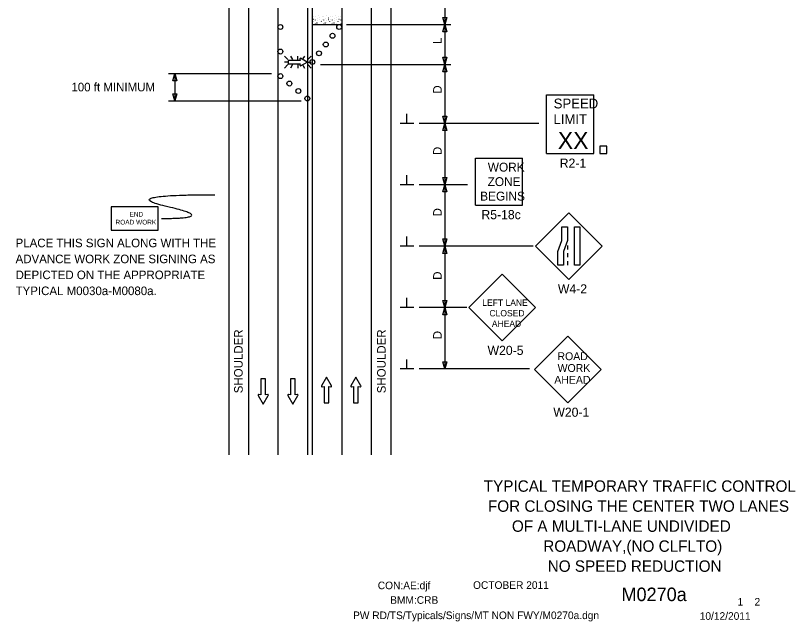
# Model space of a CAD drawing. Extents: x 16796 to 18475, y 7218 to 8209.
# Drawn here: x 16796 to 17431, y 7218 to 7712 of the extents above; entities that cross this region are included whole.
import ezdxf

# ---------------------------------------------------------------- set-up
doc = ezdxf.new("R2010")
doc.units = 0
for name, color, linetype in [('ALI_LEGAL_EX', 7, 'Continuous'), ('BORDER', 7, 'Continuous'), ('BORDER_SIGNAL_WO', 7, 'Continuous'), ('MT_SCRATCH_LEVEL_E', 7, 'Continuous'), ('PAVT_EDGE_EX', 7, 'Continuous'), ('TRAFFIC_SIGNS_PR', 7, 'Continuous'), ('TYPICAL_TEXT_DIMEN_PR', 7, 'Continuous')]:
    doc.layers.add(name, color=color, linetype=linetype)

msp = doc.modelspace()

# ---------------------------------------------------------------- linework, layer by layer
at = {"layer": 'ALI_LEGAL_EX'}
for p, q in [((17009.33, 8204.89), (17009.33, 7353.77)), ((17061.33, 8204.89), (17061.33, 7353.77))]:
    msp.add_line(p, q, dxfattribs=at)
for points in [[(17009.33, 7704.89), (17009.33, 7679.89)], [(17009.33, 7604.89), (17009.33, 7579.89)], [(17061.33, 7604.89), (17061.33, 7579.89)], [(17009.33, 7504.89), (17009.33, 7479.89)], [(17061.33, 7504.89), (17061.33, 7479.89)], [(17009.33, 7404.89), (17009.33, 7379.89)], [(17061.33, 7404.89), (17061.33, 7379.89)]]:
    msp.add_lwpolyline(points, dxfattribs=at)
at = {"layer": 'MT_SCRATCH_LEVEL_E'}
for p, q in [((16999.25, 7415.83), (16995.51, 7415.83)), ((16995.51, 7415.83), (16995.51, 7402.58)), ((16999.25, 7415.83), (16995.51, 7415.83)), ((16995.51, 7415.83), (16995.51, 7402.58)), ((16999.25, 7402.58), (16999.25, 7415.83)), ((16999.25, 7402.58), (16999.25, 7415.83)), ((17023.43, 7415.83), (17019.69, 7415.83)), ((17019.69, 7415.83), (17019.69, 7402.58)), ((17023.43, 7415.83), (17019.69, 7415.83)), ((17019.69, 7415.83), (17019.69, 7402.58)), ((17023.43, 7402.58), (17023.43, 7415.83)), ((17023.43, 7402.58), (17023.43, 7415.83)), ((17048.93, 7417.12), (17044.82, 7409.88)), ((17048.93, 7417.12), (17044.82, 7409.88)), ((17053.07, 7409.88), (17048.93, 7417.12)), ((17053.07, 7409.88), (17048.93, 7417.12)), ((17072.85, 7417.12), (17068.74, 7409.88)), ((17072.85, 7417.12), (17068.74, 7409.88)), ((17077, 7409.88), (17072.85, 7417.12)), ((17077, 7409.88), (17072.85, 7417.12)), ((17045.3, 7409.19), (17047.08, 7409.51)), ((17045.3, 7409.19), (17047.08, 7409.51)), ((17047.08, 7409.51), (17047.08, 7396.25)), ((17047.08, 7409.51), (17047.08, 7396.25)), ((17050.82, 7396.25), (17050.82, 7409.51)), ((17050.82, 7409.51), (17052.6, 7409.19)), ((17050.82, 7396.25), (17050.82, 7409.51)), ((17050.82, 7409.51), (17052.6, 7409.19)), ((17069.22, 7409.19), (17071, 7409.51)), ((17069.22, 7409.19), (17071, 7409.51)), ((17071, 7409.51), (17071, 7396.25)), ((17071, 7409.51), (17071, 7396.25)), ((17074.74, 7396.25), (17074.74, 7409.51)), ((17074.74, 7409.51), (17076.52, 7409.19)), ((17074.74, 7396.25), (17074.74, 7409.51)), ((17074.74, 7409.51), (17076.52, 7409.19)), ((16993.25, 7402.21), (16997.4, 7394.97)), ((16993.25, 7402.21), (16997.4, 7394.97)), ((16995.51, 7402.58), (16993.73, 7402.89)), ((16995.51, 7402.58), (16993.73, 7402.89)), ((16997.4, 7394.97), (17001.51, 7402.21)), ((16997.4, 7394.97), (17001.51, 7402.21)), ((17001.03, 7402.89), (16999.25, 7402.58)), ((17001.03, 7402.89), (16999.25, 7402.58)), ((17017.44, 7402.21), (17021.58, 7394.97)), ((17017.44, 7402.21), (17021.58, 7394.97)), ((17019.69, 7402.58), (17017.91, 7402.89)), ((17019.69, 7402.58), (17017.91, 7402.89)), ((17021.58, 7394.97), (17025.69, 7402.21)), ((17021.58, 7394.97), (17025.69, 7402.21)), ((17025.21, 7402.89), (17023.43, 7402.58)), ((17025.21, 7402.89), (17023.43, 7402.58)), ((17047.08, 7396.25), (17050.82, 7396.25)), ((17047.08, 7396.25), (17050.82, 7396.25)), ((17071, 7396.25), (17074.74, 7396.25)), ((17071, 7396.25), (17074.74, 7396.25))]:
    msp.add_line(p, q, dxfattribs=at)
for centre, start, end in [((17045.22, 7409.65), 150.42484, 279.96381), ((17045.22, 7409.65), 150.42484, 279.96381), ((17052.66, 7409.66), 260.03619, 29.77312), ((17052.66, 7409.66), 260.03619, 29.77312), ((17069.15, 7409.65), 150.42484, 279.96381), ((17069.15, 7409.65), 150.42484, 279.96381), ((17076.59, 7409.66), 260.03619, 29.77312), ((17076.59, 7409.66), 260.03619, 29.77312), ((16993.66, 7402.43), 80.03619, 209.77312), ((16993.66, 7402.43), 80.03619, 209.77312), ((17001.1, 7402.43), 330.42484, 99.96381), ((17001.1, 7402.43), 330.42484, 99.96381), ((17017.84, 7402.43), 80.03619, 209.77312), ((17017.84, 7402.43), 80.03619, 209.77312), ((17025.28, 7402.43), 330.42484, 99.96381), ((17025.28, 7402.43), 330.42484, 99.96381)]:
    msp.add_arc(centre, 0.463, start, end, dxfattribs=at)
at = {"layer": 'PAVT_EDGE_EX'}
for p, q in [((16969.33, 8204.89), (16969.33, 7353.77)), ((16985.33, 8204.89), (16985.33, 7353.77)), ((17085.33, 8204.89), (17085.33, 7353.77)), ((17101.33, 8204.89), (17101.33, 7353.77)), ((17033.33, 7728.31), (17033.33, 7353.77)), ((17037.33, 7728.31), (17037.33, 7353.77)), ((17042.2, 7711.53), (17042.25, 7711.45)), ((17049.09, 7711.53), (17049.14, 7711.45)), ((17055.98, 7711.53), (17056.03, 7711.45)), ((17037.81, 7706.89), (17037.86, 7707.01)), ((17038.38, 7710.85), (17038.43, 7710.77)), ((17038.43, 7708.64), (17038.48, 7708.56)), ((17039.71, 7708.07), (17039.72, 7707.95)), ((17039.91, 7710.71), (17039.96, 7710.63)), ((17040.6, 7705.65), (17040.65, 7705.57)), ((17041.33, 7705.62), (17041.38, 7705.54)), ((17041.55, 7708.92), (17041.6, 7709.04)), ((17041.74, 7707.72), (17041.79, 7707.64)), ((17043.48, 7709.79), (17043.53, 7709.71)), ((17043.52, 7708.39), (17043.57, 7708.51)), ((17044.7, 7706.89), (17044.75, 7707.01)), ((17045.27, 7710.85), (17045.32, 7710.77)), ((17045.32, 7708.64), (17045.37, 7708.56)), ((17046.6, 7708.07), (17046.61, 7707.95)), ((17046.8, 7710.71), (17046.85, 7710.63)), ((17047.48, 7705.65), (17047.53, 7705.57)), ((17048.22, 7705.62), (17048.27, 7705.54)), ((17048.44, 7708.92), (17048.49, 7709.04)), ((17048.63, 7707.72), (17048.68, 7707.64)), ((17050.37, 7709.79), (17050.42, 7709.71)), ((17050.41, 7708.39), (17050.46, 7708.51)), ((17051.59, 7706.89), (17051.64, 7707.01)), ((17052.16, 7710.85), (17052.21, 7710.77)), ((17052.21, 7708.64), (17052.26, 7708.56)), ((17053.49, 7708.07), (17053.5, 7707.95)), ((17053.69, 7710.71), (17053.74, 7710.63)), ((17054.37, 7705.65), (17054.42, 7705.57)), ((17055.11, 7705.62), (17055.16, 7705.54)), ((17055.33, 7708.92), (17055.38, 7709.04)), ((17055.52, 7707.72), (17055.57, 7707.64)), ((17057.25, 7709.79), (17057.31, 7709.71)), ((17057.3, 7708.39), (17057.35, 7708.51)), ((17058.47, 7706.89), (17058.53, 7707.01)), ((17059.04, 7710.85), (17059.1, 7710.77)), ((17059.09, 7708.64), (17059.14, 7708.56)), ((17060.37, 7708.07), (17060.39, 7707.95)), ((17060.57, 7710.71), (17060.63, 7710.63)), ((17061.26, 7705.65), (17061.31, 7705.57)), ((17037.33, 7704.33), (17061.33, 7704.33)), ((17039.83, 7704.69), (17039.88, 7704.81)), ((17043.65, 7704.39), (17043.7, 7704.51)), ((17046.72, 7704.69), (17046.77, 7704.81)), ((17050.54, 7704.39), (17050.59, 7704.51)), ((17053.61, 7704.69), (17053.66, 7704.81)), ((17057.42, 7704.39), (17057.48, 7704.51)), ((17060.49, 7704.69), (17060.55, 7704.81))]:
    msp.add_line(p, q, dxfattribs=at)
at = {"layer": 'TRAFFIC_SIGNS_PR'}
for p, q in [((17017.4, 7675.79), (17014.58, 7678.61)), ((17017.4, 7673.76), (17014.58, 7673.76)), ((17019.7, 7678.61), (17021.33, 7675.79)), ((17025.49, 7675.79), (17025.49, 7678.61)), ((17030.96, 7678.61), (17029.75, 7676.52)), ((17036.39, 7678.61), (17033.58, 7675.79)), ((17033.58, 7673.76), (17036.39, 7673.76)), ((17017.4, 7671.73), (17014.58, 7668.91)), ((17021.35, 7671.73), (17019.73, 7668.91)), ((17025.49, 7671.73), (17025.49, 7668.91)), ((17029.67, 7671.09), (17030.93, 7668.91)), ((17036.39, 7668.91), (17033.58, 7671.73)), ((17228.22, 7647.13), (17266.62, 7647.13)), ((17228.22, 7599.13), (17228.22, 7647.13)), ((17266.62, 7599.13), (17266.62, 7647.13)), ((17228.22, 7599.13), (17266.62, 7599.13)), ((17170.3, 7557.18), (17170.3, 7595.58)), ((17170.3, 7595.58), (17208.7, 7595.58)), ((17208.7, 7557.18), (17208.7, 7595.58)), ((17170.3, 7557.18), (17208.7, 7557.18)), ((17246.44, 7551), (17219.29, 7523.85)), ((17273.6, 7523.85), (17246.44, 7551)), ((17219.29, 7523.85), (17246.44, 7496.7)), ((17245.2, 7524.34), (17245.2, 7521.14)), ((17246.44, 7496.7), (17273.6, 7523.85)), ((17245.2, 7517.94), (17245.2, 7514.74)), ((17245.2, 7511.54), (17245.2, 7508.34)), ((17191.93, 7500.91), (17164.78, 7473.76)), ((17219.08, 7473.76), (17191.93, 7500.91)), ((17164.78, 7473.76), (17191.93, 7446.61)), ((17191.93, 7446.61), (17219.08, 7473.76)), ((17245.52, 7450.52), (17218.37, 7423.37)), ((17272.67, 7423.37), (17245.52, 7450.52)), ((17218.37, 7423.37), (17245.52, 7396.22)), ((17245.52, 7396.22), (17272.67, 7423.37))]:
    msp.add_line(p, q, dxfattribs=at)
for points in [[(17027.32, 7676.44), (17027.55, 7675.15), (17017.82, 7675.15), (17017.82, 7672.4), (17027.55, 7672.4), (17027.31, 7671.1)], [(17027.82, 7670.74), (17033.13, 7673.76), (17027.82, 7676.8)]]:
    msp.add_lwpolyline(points, dxfattribs=at)
for points in [[(17271.64, 7599.13), (17277.23, 7599.13), (17277.23, 7605.3), (17271.64, 7605.3)], [(16873.44, 7536.69), (16911.84, 7536.69), (16911.84, 7555.89), (16873.44, 7555.89)], [(17245.2, 7539.59), (17245.2, 7528.4), (17241.85, 7519.52), (17241.85, 7508.34), (17237.36, 7508.34), (17237.36, 7519.52), (17240.7, 7528.4), (17240.7, 7539.59)], [(17255.33, 7539.59), (17255.33, 7508.34), (17250.84, 7508.34), (17250.84, 7539.59)]]:
    msp.add_lwpolyline(points, close=True, dxfattribs=at)
for centre in [(17011.37, 7702.3), (17059.3, 7702.3), (17053.81, 7695.16), (17048.32, 7688.03), (17011.37, 7682.3), (17042.83, 7680.9), (17037.33, 7673.77), (17011.37, 7662.3), (17018.69, 7656.24), (17026.02, 7650.17), (17033.34, 7644.1)]:
    msp.add_circle(centre, 2, dxfattribs=at)
for centre, start, end in [((17027.65, 7676.5), 61.48329, 189.95933), ((17027.65, 7671.04), 170.73078, 298.89165)]:
    msp.add_arc(centre, 0.341, start, end, dxfattribs=at)
msp.add_open_spline([(16914.38, 7546.34), (16961.61, 7546.34), (16876.59, 7565.69), (16958.07, 7565.69)], degree=2, dxfattribs=at)
at = {"layer": 'TYPICAL_TEXT_DIMEN_PR'}
for p, q in [((17145.33, 7728.31), (17145.33, 7704.31)), ((17145.33, 7704.31), (17143.76, 7710.17)), ((17143.76, 7710.17), (17145.33, 7710.17)), ((17145.33, 7710.17), (17146.9, 7710.17)), ((17146.9, 7710.17), (17145.33, 7704.31)), ((17065.19, 7704.31), (17150.33, 7704.31)), ((17143.76, 7698.44), (17145.33, 7704.31)), ((17143.76, 7698.44), (17145.33, 7704.31)), ((17145.33, 7704.31), (17145.33, 7671.77)), ((17145.33, 7704.31), (17146.9, 7698.44)), ((17145.33, 7704.31), (17146.9, 7698.44)), ((17145.33, 7698.44), (17143.76, 7698.44)), ((17145.33, 7698.44), (17143.76, 7698.44)), ((17146.9, 7698.44), (17145.33, 7698.44)), ((17146.9, 7698.44), (17145.33, 7698.44)), ((17145.33, 7671.77), (17143.76, 7677.63)), ((17143.76, 7677.63), (17145.33, 7677.63)), ((17145.33, 7671.77), (17143.76, 7677.63)), ((17143.76, 7677.63), (17145.33, 7677.63)), ((17145.33, 7677.63), (17146.9, 7677.63)), ((17146.9, 7677.63), (17145.33, 7671.77)), ((17145.33, 7677.63), (17146.9, 7677.63)), ((17146.9, 7677.63), (17145.33, 7671.77)), ((17043.9, 7671.77), (17150.33, 7671.77)), ((17143.76, 7665.9), (17145.33, 7671.77)), ((17143.76, 7665.9), (17145.33, 7671.77)), ((17145.33, 7671.77), (17145.33, 7623.77)), ((17145.33, 7671.77), (17146.9, 7665.9)), ((17145.33, 7671.77), (17146.9, 7665.9)), ((16920.33, 7664.31), (17003.99, 7664.31)), ((16923.76, 7658.44), (16925.33, 7664.31)), ((16925.33, 7664.31), (16925.33, 7642.1)), ((16925.33, 7664.31), (16926.9, 7658.44)), ((17145.33, 7665.9), (17143.76, 7665.9)), ((17145.33, 7665.9), (17143.76, 7665.9)), ((17146.9, 7665.9), (17145.33, 7665.9)), ((17146.9, 7665.9), (17145.33, 7665.9)), ((16925.33, 7658.44), (16923.76, 7658.44)), ((16926.9, 7658.44), (16925.33, 7658.44)), ((16920.33, 7642.1), (17028.2, 7642.1)), ((16925.33, 7642.1), (16923.76, 7647.96)), ((16923.76, 7647.96), (16925.33, 7647.96)), ((16925.33, 7647.96), (16926.9, 7647.96)), ((16926.9, 7647.96), (16925.33, 7642.1)), ((17114.46, 7623.77), (17114.46, 7631.56)), ((17145.33, 7623.77), (17143.76, 7629.64)), ((17143.76, 7629.64), (17145.33, 7629.64)), ((17145.33, 7623.77), (17143.76, 7629.64)), ((17143.76, 7629.64), (17145.33, 7629.64)), ((17145.33, 7629.64), (17146.9, 7629.64)), ((17146.9, 7629.64), (17145.33, 7623.77)), ((17145.33, 7629.64), (17146.9, 7629.64)), ((17146.9, 7629.64), (17145.33, 7623.77)), ((17120.08, 7623.77), (17108.83, 7623.77)), ((17221.76, 7623.77), (17124.33, 7623.77)), ((17143.76, 7617.91), (17145.33, 7623.77)), ((17143.76, 7617.91), (17145.33, 7623.77)), ((17145.33, 7623.77), (17145.33, 7573.77)), ((17145.33, 7623.77), (17146.9, 7617.91)), ((17145.33, 7623.77), (17146.9, 7617.91)), ((17145.33, 7617.91), (17143.76, 7617.91)), ((17145.33, 7617.91), (17143.76, 7617.91)), ((17146.9, 7617.91), (17145.33, 7617.91)), ((17146.9, 7617.91), (17145.33, 7617.91)), ((17114.46, 7573.77), (17114.46, 7581.56)), ((17145.33, 7573.77), (17143.76, 7579.64)), ((17143.76, 7579.64), (17145.33, 7579.64)), ((17145.33, 7573.77), (17143.76, 7579.64)), ((17143.76, 7579.64), (17145.33, 7579.64)), ((17145.33, 7579.64), (17146.9, 7579.64)), ((17146.9, 7579.64), (17145.33, 7573.77)), ((17145.33, 7579.64), (17146.9, 7579.64)), ((17146.9, 7579.64), (17145.33, 7573.77)), ((17120.08, 7573.77), (17108.83, 7573.77)), ((17163.91, 7573.77), (17124.33, 7573.77)), ((17143.76, 7567.91), (17145.33, 7573.77)), ((17145.33, 7573.77), (17145.33, 7523.77)), ((17145.33, 7573.77), (17146.9, 7567.91)), ((17145.33, 7567.91), (17143.76, 7567.91)), ((17146.9, 7567.91), (17145.33, 7567.91)), ((17114.46, 7523.77), (17114.46, 7531.56)), ((17145.33, 7523.77), (17143.76, 7529.64)), ((17143.76, 7529.64), (17145.33, 7529.64)), ((17145.33, 7529.64), (17146.9, 7529.64)), ((17146.9, 7529.64), (17145.33, 7523.77)), ((17120.08, 7523.77), (17108.83, 7523.77)), ((17217.23, 7523.77), (17124.33, 7523.77)), ((17143.76, 7517.91), (17145.33, 7523.77)), ((17145.33, 7523.77), (17145.33, 7473.77)), ((17145.33, 7523.77), (17146.9, 7517.91)), ((17145.33, 7517.91), (17143.76, 7517.91)), ((17146.9, 7517.91), (17145.33, 7517.91)), ((17114.46, 7473.77), (17114.46, 7481.56)), ((17145.33, 7473.77), (17143.76, 7479.64)), ((17143.76, 7479.64), (17145.33, 7479.64)), ((17145.33, 7473.77), (17143.76, 7479.64)), ((17143.76, 7479.64), (17145.33, 7479.64)), ((17145.33, 7479.64), (17146.9, 7479.64)), ((17146.9, 7479.64), (17145.33, 7473.77)), ((17145.33, 7479.64), (17146.9, 7479.64)), ((17146.9, 7479.64), (17145.33, 7473.77)), ((17120.08, 7473.77), (17108.83, 7473.77)), ((17163.33, 7473.77), (17124.33, 7473.77)), ((17143.76, 7467.91), (17145.33, 7473.77)), ((17145.33, 7473.77), (17145.33, 7423.77)), ((17145.33, 7473.77), (17146.9, 7467.91)), ((17145.33, 7467.91), (17143.76, 7467.91)), ((17146.9, 7467.91), (17145.33, 7467.91)), ((17114.46, 7423.77), (17114.46, 7431.56)), ((17145.33, 7423.77), (17143.76, 7429.64)), ((17143.76, 7429.64), (17145.33, 7429.64)), ((17145.33, 7429.64), (17146.9, 7429.64)), ((17146.9, 7429.64), (17145.33, 7423.77)), ((17120.08, 7423.77), (17108.83, 7423.77)), ((17214.31, 7423.77), (17124.33, 7423.77))]:
    msp.add_line(p, q, dxfattribs=at)

# ---------------------------------------------------------------- texts
at = {"layer": 'BORDER'}
for s, p in [('TYPICAL TEMPORARY TRAFFIC CONTROL', (17177.02, 7323.68)), ('FOR CLOSING THE CENTER TWO LANES', (17180.44, 7307.38)), ('OF A MULTI-LANE UNDIVIDED ', (17199.96, 7291.08)), ('ROADWAY,(NO CLFLTO)', (17225.51, 7274.78)), ('NO SPEED REDUCTION', (17229.11, 7258.48))]:
    msp.add_text(s, height=9.3, dxfattribs=at).set_placement(p)
at = {"layer": 'BORDER_SIGNAL_WO'}
for s, height, p in [('CON:AE:djf', 6.2, (17090.69, 7244.31)), ('    OCTOBER 2011    ', 6.2, (17159.08, 7244.59)), ('    M0270a   ', 11, (17272.86, 7234.63)), ('BMM:CRB   ', 6.2, (17100.81, 7232.42)), (' 1    2 ', 6.2, (17381.45, 7230.95)), ('PW RD/TS/Typicals/Signs/MT NON FWY/M0270a.dgn    ', 6.2, (17070.55, 7219.96)), ('10/12/2011    ', 6.2, (17352.93, 7219.38))]:
    msp.add_text(s, height=height, dxfattribs=at).set_placement(p)
at = {"layer": 'TRAFFIC_SIGNS_PR'}
for s, height, p in [('SPEED', 8, (17233.99, 7635.99)), ('LIMIT', 8, (17233.82, 7623.19)), ('XX', 14.031, (17237.33, 7602.88)), ('WORK', 7.217, (17180.3, 7584.55)), ('R2-1', 7.44, (17238.9, 7587.69)), ('ZONE', 7.217, (17180.18, 7572.74)), ('BEGINS', 7.217, (17174.11, 7560.93)), ('R5-18c', 7.44, (17175.11, 7545.74)), ('END', 3.831, (16888.44, 7547.82)), ('ROAD WORK', 3.831, (16877.05, 7541.43)), ('PLACE THIS SIGN ALONG WITH THE', 7, (16795.65, 7522.89)), ('ADVANCE WORK ZONE SIGNING AS', 7, (16795.65, 7509.89)), ('DEPICTED ON THE APPROPRIATE', 7, (16795.65, 7496.89)), ('TYPICAL M0030a-M0080a.', 7, (16795.65, 7483.89)), ('W4-2', 7.44, (17237.4, 7485.26)), ('LEFT LANE', 5.2, (17175.81, 7475.15)), ('CLOSED', 5.2, (17181.64, 7466.56)), ('AHEAD', 5.2, (17183.59, 7457.95)), ('W20-5', 7.44, (17180.1, 7435.17)), ('ROAD', 6.4, (17237.06, 7430.91)), ('WORK', 6.4, (17237.17, 7421.31)), ('AHEAD', 6.4, (17234.48, 7411.71)), ('W20-1', 7.44, (17233.69, 7384.78))]:
    msp.add_text(s, height=height, dxfattribs=at).set_placement(p)
at = {"layer": 'TYPICAL_TEXT_DIMEN_PR'}
for s, p in [('L', (17142.78, 7688.4)), ('D', (17142.78, 7647.99)), ('D', (17142.78, 7597.99)), ('D', (17142.78, 7547.99)), ('D', (17142.78, 7496.37)), ('SHOULDER', (16980.65, 7403.93)), ('SHOULDER', (17097.15, 7403.93)), ('D', (17142.78, 7447.99))]:
    msp.add_text(s, height=7, rotation=90, dxfattribs=at).set_placement(p)
msp.add_text('100 ft MINIMUM', height=7, dxfattribs=at).set_placement((16841.12, 7649.89))

doc.saveas('drawing.dxf')
